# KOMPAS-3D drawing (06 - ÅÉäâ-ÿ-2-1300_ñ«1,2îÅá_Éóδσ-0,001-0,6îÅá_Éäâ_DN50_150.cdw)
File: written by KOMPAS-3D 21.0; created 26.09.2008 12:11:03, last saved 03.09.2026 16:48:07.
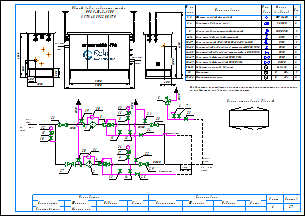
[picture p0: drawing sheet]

Sheets 1-2: A3, landscape

Document properties: Наименование: Макро:21; Автор: RaskoAdmin; Форматы листов документа: 2xA3; Полное имя файла: \\UR38nt01\Departments\КТО\КБ ПУРДГ\Заявки\Прайс-лист на типовые шкафы ГРПШ\ПРДГ_стандарт_20_03_2026\ПРДГ с РДГ(Н, В)\ПРДГ-Ш-2-1300_до1,2МПа_Рвых-0,001-0,6МПа_РДГ_DN50_150.cdw

Title block, sheet 1: Наименование: Пункт учета газа / ПУГ-Ш-400-Р / ЛГТИ.485922.001ТУ; designation: ЛГТИ.03.4411141; sheet number: 1; Количество листов документа: 2; organisation: ООО "ЭЛЬСТЕР Газэлектроника"; Форматы листов документа: A3; stored path: C:\Рабочие документы\Компас\ПУГ\Схема.cdw; Разработал: Устинов; Проверил: Кошкин; Утвердил: Кошкин
Title block, sheet 2: sheet number: 2; stored path: D:\Рабочие документы\Заявки\ПУРДГ\ПУРДГ-ШУЭО-2-100-Р 4411220.cdw; designation, second copy: ЛГТИ.03.4411141-

Views: Вид 1, Вид 2
Referenced files: wcvoit.frw
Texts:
  Normal
  № на
  схеме
  Усл.
  обозн.
  Марка
  (модель)
  Кол.
  Фильтр газовый фланцевый
  ФГ 16-50
  Регулятор давления газа
  РДГ-50
  Клапан предохранительный сбросной
  КПС DN20
  Кран шаровой газовый латунный
  DN15
  Кран кнопочный VE-РАСКО-НЗ-1,6-G1/2-М20
  Кран шаровой "под приварку" штуцерный DN20 PN16
  Кран шаровой "под приварку" штуцерный п/п DN20 PN16
  DN20
  Кран шаровой фланцевый DN50 PN16
  Кран шаровой фланцевый DN150 PN16
  DN50
  DN150
  Индикатор перепада давления
  Delta 15
  Манометр
  Манометр-напоромер
  0...     МПа
  0...     кПа
  Общий вид и габариты шкафа
  ПРДГ-Ш-2-1300
  Выход газа
  Вход газа
  Схема открывания дверей
  logo-rasko-ge.png
  Предприятие изготовитель может заменять комплектующие на аналогичные,
  не ухудшающие заявленных характеристик.
  Вход
  газа
  PDI
  Выход
  Р=     кПа
  Импульс DN20
  ≥5DN
  HYSWLongFangSong
  Р=       МПа
  Должность
  Конструктор
  Фамилия
  Подпись
  Дата
  Согласовано
  Максимкин
  Лист
  Листов
  POLYLINE_STYLE_0.18_RGB_0_0_0
  POLYLINE_STYLE_0.50_RGB_0_0_0
  POLYLINE_STYLE_0.34_RGB_0_0_0
  PHANTOM_RGB_0_0_0_SC_1_THICK_0.18
  K5LT_THIN_RGB_0_0_0_THICK_0.18
  K5LT32769_RGB_0_0_0_THICK_0.18
  K5LT12_RGB_0_0_0_SC_1_THICK_0.18
  K5LT_DASHED_RGB_0_0_0_SC_1_THICK_0.18
  ACISOTGL_RGB_0_0_0_SC_0.8_THICK_0.25
  CONTINUOUS_RGB_0_127_31_THICK_0.3
  CONTINUOUS_RGB_0_0_255_THICK_0.35
  CONTINUOUS_RGB_255_0_0_THICK_0.35
  POLYLINE_STYLE_0.25_RGB_0_0_0
  CONTINUOUS_RGB_0_0_0_THICK_0.5
  POLYLINE_STYLE_0.35_RGB_0_0_255
  CONTINUOUS_RGB_0_0_0_THICK_0.4
  CONTINUOUS_RGB_0_0_0_THICK_0.35
  Без оформления
Dimensions and other numbers on the sheet: 1; 1, 2; 2; 3, 4; 5; 6-14; 9; 15-17; 3; 18-23; 24-25; 6; 26-27; 28-29; 30-31; 32; 33-34; 400; 1050; 500; 305; 1565; 3300; 1000; 4130; 3000; 4; 10; 27; 28; 29; 23; 8; 12; 19; 20; 21; 22; 25; 24; 30; 31; 15; 16; 26; 7; 11; 14; 13; 33; 17; 34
